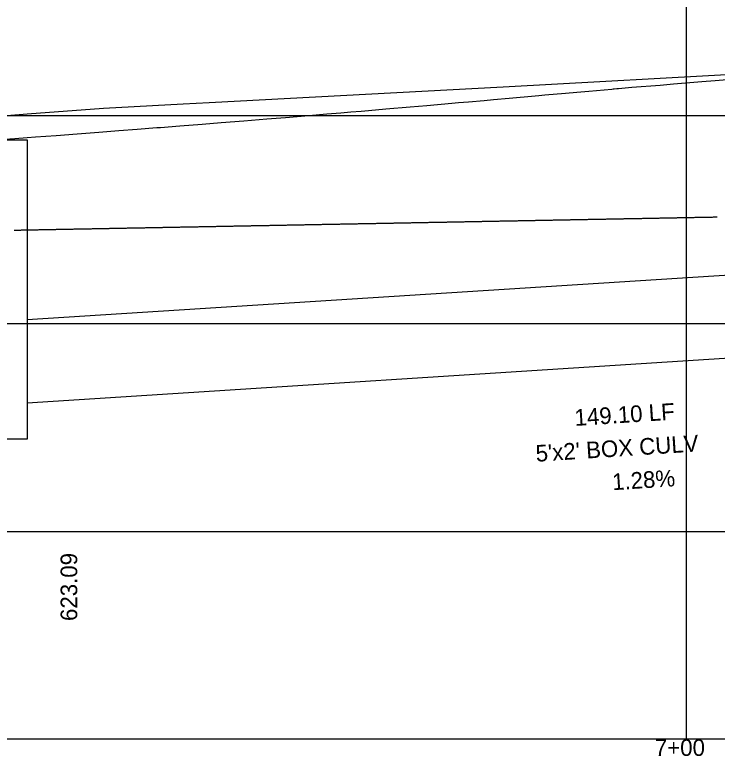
# Model space of a CAD drawing. Extents: x 2254979 to 2278074, y 13790855 to 13792793.
# Drawn here: x 2260580 to 2260664.4, y 13792139.4 to 13792228.5 of the extents above; entities that cross this region are included whole.
import ezdxf

# ---------------------------------------------------------------- set-up
doc = ezdxf.new("R2010")
doc.units = 0
for name, color, linetype in [('blank4', 7, 'Continuous'), ('D_DRN_PROF_HGL', 7, 'Continuous'), ('D_PROF_1', 7, 'Continuous'), ('D_PROF_NOTES_1', 7, 'Continuous'), ('Default', 7, 'Continuous'), ('Drain_PipeInside', 7, 'Continuous'), ('E_Terrain', 7, 'Continuous'), ('Inlet', 7, 'Continuous'), ('z - Construction', 7, 'Continuous')]:
    doc.layers.add(name, color=color, linetype=linetype)

msp = doc.modelspace()

# ---------------------------------------------------------------- linework, layer by layer
at = {"layer": 'blank4'}
msp.add_lwpolyline([(2259960.685, 13792141.443), (2259960.685, 13792316.443), (2261351.477, 13792316.443), (2261351.477, 13792141.443)], close=True, dxfattribs=at)
at = {"layer": 'D_DRN_PROF_HGL'}
msp.add_lwpolyline([(2260579.903, 13792202.657), (2260580.014, 13792202.66), (2260580.124, 13792202.662), (2260580.235, 13792202.664), (2260580.345, 13792202.666), (2260580.456, 13792202.668), (2260580.567, 13792202.67), (2260580.677, 13792202.672), (2260580.788, 13792202.674), (2260580.898, 13792202.676), (2260581.009, 13792202.678), (2260581.119, 13792202.68), (2260581.23, 13792202.682), (2260581.341, 13792202.684), (2260581.451, 13792202.687), (2260581.562, 13792202.689), (2260581.672, 13792202.691), (2260581.783, 13792202.693), (2260581.893, 13792202.695), (2260582.004, 13792202.697), (2260582.115, 13792202.699), (2260582.225, 13792202.701), (2260582.336, 13792202.703), (2260582.446, 13792202.705), (2260582.557, 13792202.707), (2260582.667, 13792202.709), (2260582.778, 13792202.712), (2260582.889, 13792202.714), (2260582.999, 13792202.716), (2260583.11, 13792202.718), (2260583.22, 13792202.72), (2260583.331, 13792202.722), (2260583.441, 13792202.724), (2260583.552, 13792202.726), (2260583.663, 13792202.728), (2260583.773, 13792202.73), (2260583.884, 13792202.732), (2260583.994, 13792202.734), (2260584.105, 13792202.736), (2260584.215, 13792202.739), (2260584.326, 13792202.741), (2260584.437, 13792202.743), (2260584.547, 13792202.745), (2260584.658, 13792202.747), (2260584.768, 13792202.749), (2260584.879, 13792202.751), (2260584.99, 13792202.753), (2260585.1, 13792202.755), (2260585.211, 13792202.757), (2260585.321, 13792202.759), (2260585.432, 13792202.761), (2260585.542, 13792202.763), (2260585.653, 13792202.766), (2260585.764, 13792202.768), (2260585.874, 13792202.77), (2260585.985, 13792202.772), (2260586.095, 13792202.774), (2260586.206, 13792202.776), (2260586.316, 13792202.778), (2260586.427, 13792202.78), (2260586.538, 13792202.782), (2260586.648, 13792202.784), (2260586.759, 13792202.786), (2260586.869, 13792202.788), (2260586.98, 13792202.791), (2260587.09, 13792202.793), (2260587.201, 13792202.795), (2260587.312, 13792202.797), (2260587.422, 13792202.799), (2260587.533, 13792202.801), (2260587.643, 13792202.803), (2260587.754, 13792202.805), (2260587.864, 13792202.807), (2260587.975, 13792202.809), (2260588.086, 13792202.811), (2260588.196, 13792202.813), (2260588.307, 13792202.815), (2260588.417, 13792202.818), (2260588.528, 13792202.82), (2260588.638, 13792202.822), (2260588.749, 13792202.824), (2260588.86, 13792202.826), (2260588.97, 13792202.828), (2260589.081, 13792202.83), (2260589.191, 13792202.832), (2260589.302, 13792202.834), (2260589.412, 13792202.836), (2260589.523, 13792202.838), (2260589.634, 13792202.84), (2260589.744, 13792202.842), (2260589.855, 13792202.845), (2260589.965, 13792202.847), (2260590.076, 13792202.849), (2260590.187, 13792202.851), (2260590.297, 13792202.853), (2260590.408, 13792202.855), (2260590.518, 13792202.857), (2260590.629, 13792202.859), (2260590.739, 13792202.861), (2260590.85, 13792202.863), (2260590.961, 13792202.865), (2260591.071, 13792202.867), (2260591.182, 13792202.869), (2260591.292, 13792202.872), (2260591.403, 13792202.874), (2260591.513, 13792202.876), (2260591.624, 13792202.878), (2260591.735, 13792202.88), (2260591.845, 13792202.882), (2260591.956, 13792202.884), (2260592.066, 13792202.886), (2260592.177, 13792202.888), (2260592.287, 13792202.89), (2260592.398, 13792202.892), (2260592.509, 13792202.894), (2260592.619, 13792202.897), (2260592.73, 13792202.899), (2260592.84, 13792202.901), (2260592.951, 13792202.903), (2260593.061, 13792202.905), (2260593.172, 13792202.907), (2260593.283, 13792202.909), (2260593.393, 13792202.911), (2260593.504, 13792202.913), (2260593.614, 13792202.915), (2260593.725, 13792202.917), (2260593.835, 13792202.919), (2260593.946, 13792202.921), (2260594.057, 13792202.924), (2260594.167, 13792202.926), (2260594.278, 13792202.928), (2260594.388, 13792202.93), (2260594.499, 13792202.932), (2260594.609, 13792202.934), (2260594.72, 13792202.936), (2260594.831, 13792202.938), (2260594.941, 13792202.94), (2260595.052, 13792202.942), (2260595.162, 13792202.944), (2260595.273, 13792202.946), (2260595.384, 13792202.948), (2260595.494, 13792202.951), (2260595.605, 13792202.953), (2260595.715, 13792202.955), (2260595.826, 13792202.957), (2260595.936, 13792202.959), (2260596.047, 13792202.961), (2260596.158, 13792202.963), (2260596.268, 13792202.965), (2260596.379, 13792202.967), (2260596.489, 13792202.969), (2260596.6, 13792202.971), (2260596.71, 13792202.973), (2260596.821, 13792202.976), (2260596.932, 13792202.978), (2260597.042, 13792202.98), (2260597.153, 13792202.982), (2260597.263, 13792202.984), (2260597.374, 13792202.986), (2260597.484, 13792202.988), (2260597.595, 13792202.99), (2260597.706, 13792202.992), (2260597.816, 13792202.994), (2260597.927, 13792202.996), (2260598.037, 13792202.998), (2260598.148, 13792203), (2260598.258, 13792203.003), (2260598.369, 13792203.005), (2260598.48, 13792203.007), (2260598.59, 13792203.009), (2260598.701, 13792203.011), (2260598.811, 13792203.013), (2260598.922, 13792203.015), (2260599.032, 13792203.017), (2260599.143, 13792203.019), (2260599.254, 13792203.021), (2260599.364, 13792203.023), (2260599.475, 13792203.025), (2260599.585, 13792203.027), (2260599.696, 13792203.03), (2260599.806, 13792203.032), (2260599.917, 13792203.034), (2260600.028, 13792203.036), (2260600.138, 13792203.038), (2260600.249, 13792203.04), (2260600.359, 13792203.042), (2260600.47, 13792203.044), (2260600.581, 13792203.046), (2260600.691, 13792203.048), (2260600.802, 13792203.05), (2260600.912, 13792203.052), (2260601.023, 13792203.054), (2260601.133, 13792203.057), (2260601.244, 13792203.059), (2260601.355, 13792203.061), (2260601.465, 13792203.063), (2260601.576, 13792203.065), (2260601.686, 13792203.067), (2260601.797, 13792203.069), (2260601.907, 13792203.071), (2260602.018, 13792203.073), (2260602.129, 13792203.075), (2260602.239, 13792203.077), (2260602.35, 13792203.079), (2260602.46, 13792203.082), (2260602.571, 13792203.084), (2260602.681, 13792203.086), (2260602.792, 13792203.088), (2260602.903, 13792203.09), (2260603.013, 13792203.092), (2260603.124, 13792203.094), (2260603.234, 13792203.096), (2260603.345, 13792203.098), (2260603.455, 13792203.1), (2260603.566, 13792203.102), (2260603.677, 13792203.104), (2260603.787, 13792203.106), (2260603.898, 13792203.109), (2260604.008, 13792203.111), (2260604.119, 13792203.113), (2260604.229, 13792203.115), (2260604.34, 13792203.117), (2260604.451, 13792203.119), (2260604.561, 13792203.121), (2260604.672, 13792203.123), (2260604.782, 13792203.125), (2260604.893, 13792203.127), (2260605.003, 13792203.129), (2260605.114, 13792203.131), (2260605.225, 13792203.133), (2260605.335, 13792203.136), (2260605.446, 13792203.138), (2260605.556, 13792203.14), (2260605.667, 13792203.142), (2260605.778, 13792203.144), (2260605.888, 13792203.146), (2260605.999, 13792203.148), (2260606.109, 13792203.15), (2260606.22, 13792203.152), (2260606.33, 13792203.154), (2260606.441, 13792203.156), (2260606.552, 13792203.158), (2260606.662, 13792203.16), (2260606.773, 13792203.163), (2260606.883, 13792203.165), (2260606.994, 13792203.167), (2260607.104, 13792203.169), (2260607.215, 13792203.171), (2260607.326, 13792203.173), (2260607.436, 13792203.175), (2260607.547, 13792203.177), (2260607.657, 13792203.179), (2260607.768, 13792203.181), (2260607.878, 13792203.183), (2260607.989, 13792203.185), (2260608.1, 13792203.188), (2260608.21, 13792203.19), (2260608.321, 13792203.192), (2260608.431, 13792203.194), (2260608.542, 13792203.196), (2260608.652, 13792203.198), (2260608.763, 13792203.2), (2260608.874, 13792203.202), (2260608.984, 13792203.204), (2260609.095, 13792203.206), (2260609.205, 13792203.208), (2260609.316, 13792203.21), (2260609.426, 13792203.212), (2260609.537, 13792203.215), (2260609.648, 13792203.217), (2260609.758, 13792203.219), (2260609.869, 13792203.221), (2260609.979, 13792203.223), (2260610.09, 13792203.225), (2260610.2, 13792203.227), (2260610.311, 13792203.229), (2260610.422, 13792203.231), (2260610.532, 13792203.233), (2260610.643, 13792203.235), (2260610.753, 13792203.237), (2260610.864, 13792203.239), (2260610.975, 13792203.242), (2260611.085, 13792203.244), (2260611.196, 13792203.246), (2260611.306, 13792203.248), (2260611.417, 13792203.25), (2260611.527, 13792203.252), (2260611.638, 13792203.254), (2260611.749, 13792203.256), (2260611.859, 13792203.258), (2260611.97, 13792203.26), (2260612.08, 13792203.262), (2260612.191, 13792203.264), (2260612.301, 13792203.267), (2260612.412, 13792203.269), (2260612.523, 13792203.271), (2260612.633, 13792203.273), (2260612.744, 13792203.275), (2260612.854, 13792203.277), (2260612.965, 13792203.279), (2260613.075, 13792203.281), (2260613.186, 13792203.283), (2260613.297, 13792203.285), (2260613.407, 13792203.287), (2260613.518, 13792203.289), (2260613.628, 13792203.291), (2260613.739, 13792203.294), (2260613.849, 13792203.296), (2260613.96, 13792203.298), (2260614.071, 13792203.3), (2260614.181, 13792203.302), (2260614.292, 13792203.304), (2260614.402, 13792203.306), (2260614.513, 13792203.308), (2260614.623, 13792203.31), (2260614.734, 13792203.312), (2260614.845, 13792203.314), (2260614.955, 13792203.316), (2260615.066, 13792203.318), (2260615.176, 13792203.321), (2260615.287, 13792203.323), (2260615.397, 13792203.325), (2260615.508, 13792203.327), (2260615.619, 13792203.329), (2260615.729, 13792203.331), (2260615.84, 13792203.333), (2260615.95, 13792203.335), (2260616.061, 13792203.337), (2260616.172, 13792203.339), (2260616.282, 13792203.341), (2260616.393, 13792203.343), (2260616.503, 13792203.345), (2260616.614, 13792203.348), (2260616.724, 13792203.35), (2260616.835, 13792203.352), (2260616.946, 13792203.354), (2260617.056, 13792203.356), (2260617.167, 13792203.358), (2260617.277, 13792203.36), (2260617.388, 13792203.362), (2260617.498, 13792203.364), (2260617.609, 13792203.366), (2260617.72, 13792203.368), (2260617.83, 13792203.37), (2260617.941, 13792203.373), (2260618.051, 13792203.375), (2260618.162, 13792203.377), (2260618.272, 13792203.379), (2260618.383, 13792203.381), (2260618.494, 13792203.383), (2260618.604, 13792203.385), (2260618.715, 13792203.387), (2260618.825, 13792203.389), (2260618.936, 13792203.391), (2260619.046, 13792203.393), (2260619.157, 13792203.395), (2260619.268, 13792203.397), (2260619.378, 13792203.4), (2260619.489, 13792203.402), (2260619.599, 13792203.404), (2260619.71, 13792203.406), (2260619.82, 13792203.408), (2260619.931, 13792203.41), (2260620.042, 13792203.412), (2260620.152, 13792203.414), (2260620.263, 13792203.416), (2260620.373, 13792203.418), (2260620.484, 13792203.42), (2260620.594, 13792203.422), (2260620.705, 13792203.424), (2260620.816, 13792203.427), (2260620.926, 13792203.429), (2260621.037, 13792203.431), (2260621.147, 13792203.433), (2260621.258, 13792203.435), (2260621.368, 13792203.437), (2260621.479, 13792203.439), (2260621.59, 13792203.441), (2260621.7, 13792203.443), (2260621.811, 13792203.445), (2260621.921, 13792203.447), (2260622.032, 13792203.449), (2260622.143, 13792203.452), (2260622.253, 13792203.454), (2260622.364, 13792203.456), (2260622.474, 13792203.458), (2260622.585, 13792203.46), (2260622.695, 13792203.462), (2260622.806, 13792203.464), (2260622.917, 13792203.466), (2260623.027, 13792203.468), (2260623.138, 13792203.47), (2260623.248, 13792203.472), (2260623.359, 13792203.474), (2260623.469, 13792203.476), (2260623.58, 13792203.479), (2260623.691, 13792203.481), (2260623.801, 13792203.483), (2260623.912, 13792203.485), (2260624.022, 13792203.487), (2260624.133, 13792203.489), (2260624.243, 13792203.491), (2260624.354, 13792203.493), (2260624.465, 13792203.495), (2260624.575, 13792203.497), (2260624.686, 13792203.499), (2260624.796, 13792203.501), (2260624.907, 13792203.503), (2260625.017, 13792203.506), (2260625.128, 13792203.508), (2260625.239, 13792203.51), (2260625.349, 13792203.512), (2260625.46, 13792203.514), (2260625.57, 13792203.516), (2260625.681, 13792203.518), (2260625.791, 13792203.52), (2260625.902, 13792203.522), (2260626.013, 13792203.524), (2260626.123, 13792203.526), (2260626.234, 13792203.528), (2260626.344, 13792203.53), (2260626.455, 13792203.533), (2260626.565, 13792203.535), (2260626.676, 13792203.537), (2260626.787, 13792203.539), (2260626.897, 13792203.541), (2260627.008, 13792203.543), (2260627.118, 13792203.545), (2260627.229, 13792203.547), (2260627.34, 13792203.549), (2260627.45, 13792203.551), (2260627.561, 13792203.553), (2260627.671, 13792203.555), (2260627.782, 13792203.558), (2260627.892, 13792203.56), (2260628.003, 13792203.562), (2260628.114, 13792203.564), (2260628.224, 13792203.566), (2260628.335, 13792203.568), (2260628.445, 13792203.57), (2260628.556, 13792203.572), (2260628.666, 13792203.574), (2260628.777, 13792203.576), (2260628.888, 13792203.578), (2260628.998, 13792203.58), (2260629.109, 13792203.582), (2260629.219, 13792203.585), (2260629.33, 13792203.587), (2260629.44, 13792203.589), (2260629.551, 13792203.591), (2260629.662, 13792203.593), (2260629.772, 13792203.595), (2260629.883, 13792203.597), (2260629.993, 13792203.599), (2260630.104, 13792203.601), (2260630.214, 13792203.603), (2260630.325, 13792203.605), (2260630.436, 13792203.607), (2260630.546, 13792203.609), (2260630.657, 13792203.612), (2260630.767, 13792203.614), (2260630.878, 13792203.616), (2260630.988, 13792203.618), (2260631.099, 13792203.62), (2260631.21, 13792203.622), (2260631.32, 13792203.624), (2260631.431, 13792203.626), (2260631.541, 13792203.628), (2260631.652, 13792203.63), (2260631.762, 13792203.632), (2260631.873, 13792203.634), (2260631.984, 13792203.637), (2260632.094, 13792203.639), (2260632.205, 13792203.641), (2260632.315, 13792203.643), (2260632.426, 13792203.645), (2260632.537, 13792203.647), (2260632.647, 13792203.649), (2260632.758, 13792203.651), (2260632.868, 13792203.653), (2260632.979, 13792203.655), (2260633.089, 13792203.657), (2260633.2, 13792203.659), (2260633.311, 13792203.661), (2260633.421, 13792203.664), (2260633.532, 13792203.666), (2260633.642, 13792203.668), (2260633.753, 13792203.67), (2260633.863, 13792203.672), (2260633.974, 13792203.674), (2260634.085, 13792203.676), (2260634.195, 13792203.678), (2260634.306, 13792203.68), (2260634.416, 13792203.682), (2260634.527, 13792203.684), (2260634.637, 13792203.686), (2260634.748, 13792203.688), (2260634.859, 13792203.691), (2260634.969, 13792203.693), (2260635.08, 13792203.695), (2260635.19, 13792203.697), (2260635.301, 13792203.699), (2260635.411, 13792203.701), (2260635.522, 13792203.703), (2260635.633, 13792203.705), (2260635.743, 13792203.707), (2260635.854, 13792203.709), (2260635.964, 13792203.711), (2260636.075, 13792203.713), (2260636.185, 13792203.715), (2260636.296, 13792203.718), (2260636.407, 13792203.72), (2260636.517, 13792203.722), (2260636.628, 13792203.724), (2260636.738, 13792203.726), (2260636.849, 13792203.728), (2260636.959, 13792203.73), (2260637.07, 13792203.732), (2260637.181, 13792203.734), (2260637.291, 13792203.736), (2260637.402, 13792203.738), (2260637.512, 13792203.74), (2260637.623, 13792203.743), (2260637.734, 13792203.745), (2260637.844, 13792203.747), (2260637.955, 13792203.749), (2260638.065, 13792203.751), (2260638.176, 13792203.753), (2260638.286, 13792203.755), (2260638.397, 13792203.757), (2260638.508, 13792203.759), (2260638.618, 13792203.761), (2260638.729, 13792203.763), (2260638.839, 13792203.765), (2260638.95, 13792203.767), (2260639.06, 13792203.77), (2260639.171, 13792203.772), (2260639.282, 13792203.774), (2260639.392, 13792203.776), (2260639.503, 13792203.778), (2260639.613, 13792203.78), (2260639.724, 13792203.782), (2260639.834, 13792203.784), (2260639.945, 13792203.786), (2260640.056, 13792203.788), (2260640.166, 13792203.79), (2260640.277, 13792203.792), (2260640.387, 13792203.794), (2260640.498, 13792203.797), (2260640.608, 13792203.799), (2260640.719, 13792203.801), (2260640.83, 13792203.803), (2260640.94, 13792203.805), (2260641.051, 13792203.807), (2260641.161, 13792203.809), (2260641.272, 13792203.811), (2260641.382, 13792203.813), (2260641.493, 13792203.815), (2260641.604, 13792203.817), (2260641.714, 13792203.819), (2260641.825, 13792203.821), (2260641.935, 13792203.824), (2260642.046, 13792203.826), (2260642.156, 13792203.828), (2260642.267, 13792203.83), (2260642.378, 13792203.832), (2260642.488, 13792203.834), (2260642.599, 13792203.836), (2260642.709, 13792203.838), (2260642.82, 13792203.84), (2260642.931, 13792203.842), (2260643.041, 13792203.844), (2260643.152, 13792203.846), (2260643.262, 13792203.849), (2260643.373, 13792203.851), (2260643.483, 13792203.853), (2260643.594, 13792203.855), (2260643.705, 13792203.857), (2260643.815, 13792203.859), (2260643.926, 13792203.861), (2260644.036, 13792203.863), (2260644.147, 13792203.865), (2260644.257, 13792203.867), (2260644.368, 13792203.869), (2260644.479, 13792203.871), (2260644.589, 13792203.873), (2260644.7, 13792203.876), (2260644.81, 13792203.878), (2260644.921, 13792203.88), (2260645.031, 13792203.882), (2260645.142, 13792203.884), (2260645.253, 13792203.886), (2260645.363, 13792203.888), (2260645.474, 13792203.89), (2260645.584, 13792203.892), (2260645.695, 13792203.894), (2260645.805, 13792203.896), (2260645.916, 13792203.898), (2260646.027, 13792203.9), (2260646.137, 13792203.903), (2260646.248, 13792203.905), (2260646.358, 13792203.907), (2260646.469, 13792203.909), (2260646.579, 13792203.911), (2260646.69, 13792203.913), (2260646.801, 13792203.915), (2260646.911, 13792203.917), (2260647.022, 13792203.919), (2260647.132, 13792203.921), (2260647.243, 13792203.923), (2260647.353, 13792203.925), (2260647.464, 13792203.928), (2260647.575, 13792203.93), (2260647.685, 13792203.932), (2260647.796, 13792203.934), (2260647.906, 13792203.936), (2260648.017, 13792203.938), (2260648.128, 13792203.94), (2260648.238, 13792203.942), (2260648.349, 13792203.944), (2260648.459, 13792203.946), (2260648.57, 13792203.948), (2260648.68, 13792203.95), (2260648.791, 13792203.952), (2260648.902, 13792203.955), (2260649.012, 13792203.957), (2260649.123, 13792203.959), (2260649.233, 13792203.961), (2260649.344, 13792203.963), (2260649.454, 13792203.965), (2260649.565, 13792203.967), (2260649.676, 13792203.969), (2260649.786, 13792203.971), (2260649.897, 13792203.973), (2260650.007, 13792203.975), (2260650.118, 13792203.977), (2260650.228, 13792203.979), (2260650.339, 13792203.982), (2260650.45, 13792203.984), (2260650.56, 13792203.986), (2260650.671, 13792203.988), (2260650.781, 13792203.99), (2260650.892, 13792203.992), (2260651.002, 13792203.994), (2260651.113, 13792203.996), (2260651.224, 13792203.998), (2260651.334, 13792204), (2260651.445, 13792204.002), (2260651.555, 13792204.004), (2260651.666, 13792204.006), (2260651.776, 13792204.009), (2260651.887, 13792204.011), (2260651.998, 13792204.013), (2260652.108, 13792204.015), (2260652.219, 13792204.017), (2260652.329, 13792204.019), (2260652.44, 13792204.021), (2260652.55, 13792204.023), (2260652.661, 13792204.025), (2260652.772, 13792204.027), (2260652.882, 13792204.029), (2260652.993, 13792204.031), (2260653.103, 13792204.034), (2260653.214, 13792204.036), (2260653.325, 13792204.038), (2260653.435, 13792204.04), (2260653.546, 13792204.042), (2260653.656, 13792204.044), (2260653.767, 13792204.046), (2260653.877, 13792204.048), (2260653.988, 13792204.05), (2260654.099, 13792204.052), (2260654.209, 13792204.054), (2260654.32, 13792204.056), (2260654.43, 13792204.058), (2260654.541, 13792204.061), (2260654.651, 13792204.063), (2260654.762, 13792204.065), (2260654.873, 13792204.067), (2260654.983, 13792204.069), (2260655.094, 13792204.071), (2260655.204, 13792204.073), (2260655.315, 13792204.075), (2260655.425, 13792204.077), (2260655.536, 13792204.079), (2260655.647, 13792204.081), (2260655.757, 13792204.083), (2260655.868, 13792204.085), (2260655.978, 13792204.088), (2260656.089, 13792204.09), (2260656.199, 13792204.092), (2260656.31, 13792204.094), (2260656.421, 13792204.096), (2260656.531, 13792204.098), (2260656.642, 13792204.1), (2260656.752, 13792204.102), (2260656.863, 13792204.104), (2260656.973, 13792204.106), (2260657.084, 13792204.108), (2260657.195, 13792204.11), (2260657.305, 13792204.113), (2260657.416, 13792204.115), (2260657.526, 13792204.117), (2260657.637, 13792204.119), (2260657.747, 13792204.121), (2260657.858, 13792204.123), (2260657.969, 13792204.125), (2260658.079, 13792204.127), (2260658.19, 13792204.129), (2260658.3, 13792204.131), (2260658.411, 13792204.133), (2260658.522, 13792204.135), (2260658.632, 13792204.137), (2260658.743, 13792204.14), (2260658.853, 13792204.142), (2260658.964, 13792204.144), (2260659.074, 13792204.146), (2260659.185, 13792204.148), (2260659.296, 13792204.15), (2260659.406, 13792204.152), (2260659.517, 13792204.154), (2260659.627, 13792204.156), (2260659.738, 13792204.158), (2260659.848, 13792204.16), (2260659.959, 13792204.162), (2260660.07, 13792204.164), (2260660.18, 13792204.167), (2260660.291, 13792204.169), (2260660.401, 13792204.171), (2260660.512, 13792204.173), (2260660.622, 13792204.175), (2260660.733, 13792204.177), (2260660.844, 13792204.179), (2260660.954, 13792204.181), (2260661.065, 13792204.183), (2260661.175, 13792204.185), (2260661.286, 13792204.187), (2260661.396, 13792204.189), (2260661.507, 13792204.191), (2260661.618, 13792204.194), (2260661.728, 13792204.196), (2260661.839, 13792204.198), (2260661.949, 13792204.2), (2260662.06, 13792204.202), (2260662.17, 13792204.204), (2260662.281, 13792204.206), (2260662.392, 13792204.208), (2260662.502, 13792204.21), (2260662.613, 13792204.212), (2260662.723, 13792204.214), (2260662.834, 13792204.216), (2260662.944, 13792204.219), (2260663.055, 13792204.221), (2260663.166, 13792204.223), (2260663.276, 13792204.225), (2260663.387, 13792204.227), (2260663.497, 13792204.229), (2260663.608, 13792204.231), (2260663.719, 13792204.233), (2260663.829, 13792204.235), (2260663.94, 13792204.237), (2260664.05, 13792204.239), (2260664.161, 13792204.241), (2260664.271, 13792204.243), (2260664.382, 13792204.246)], dxfattribs=at)
at = {"layer": 'D_PROF_1'}
msp.add_lwpolyline([(2260577.47, 13792213.497), (2260579.97, 13792213.681), (2260581.47, 13792213.791), (2260581.47, 13792213.791), (2260582.471, 13792213.865), (2260584.941, 13792214.05), (2260587.472, 13792214.24), (2260590.048, 13792214.436), (2260592.473, 13792214.621), (2260594.657, 13792214.791), (2260597.053, 13792214.977), (2260597.252, 13792214.992), (2260597.474, 13792215.009), (2260599.807, 13792215.194), (2260602.476, 13792215.405), (2260604.762, 13792215.589), (2260607.479, 13792215.807), (2260610.251, 13792216.033), (2260612.482, 13792216.216), (2260615.31, 13792216.45), (2260617.485, 13792216.632), (2260619.135, 13792216.77), (2260620.359, 13792216.873), (2260621.594, 13792216.978), (2260622.489, 13792217.054), (2260624.554, 13792217.232), (2260627.493, 13792217.484), (2260629.496, 13792217.659), (2260632.498, 13792217.92), (2260633.279, 13792217.989), (2260634.5, 13792218.096), (2260636.357, 13792218.26), (2260637.503, 13792218.362), (2260639.37, 13792218.527), (2260642.509, 13792218.804), (2260642.932, 13792218.842), (2260643.676, 13792218.908), (2260646.156, 13792219.127), (2260647.513, 13792219.247), (2260648.965, 13792219.375), (2260651.717, 13792219.619), (2260651.889, 13792219.634), (2260651.977, 13792219.642), (2260652.336, 13792219.673), (2260652.517, 13792219.689), (2260654.138, 13792219.825), (2260657.52, 13792220.102), (2260659.128, 13792220.237), (2260662.524, 13792220.515), (2260664.12, 13792220.649), (2260667.527, 13792220.928)], dxfattribs=at)
at = {"layer": 'Default'}
msp.add_line((2260660.685, 13792141.443), (2260660.685, 13792316.443), dxfattribs=at)
at = {"layer": 'Drain_PipeInside'}
for p, q in [((2260581.47, 13792191.898), (2260730.572, 13792201.443)), ((2260581.47, 13792181.898), (2260730.572, 13792191.443))]:
    msp.add_line(p, q, dxfattribs=at)
at = {"layer": 'E_Terrain'}
msp.add_lwpolyline([(2260577.47, 13792216.305), (2260581.47, 13792216.628), (2260581.47, 13792216.628), (2260590.632, 13792217.322), (2260600.206, 13792217.86), (2260603.32, 13792218.014), (2260638.64, 13792219.874), (2260669.149, 13792221.582), (2260700.382, 13792223.474), (2260700.415, 13792223.257), (2260730.572, 13792225.385), (2260730.572, 13792225.385), (2260734.572, 13792225.81), (2260734.572, 13792225.81), (2260738.572, 13792226.234)], dxfattribs=at)
at = {"layer": 'Inlet'}
msp.add_lwpolyline([(2260573.47, 13792213.497), (2260581.47, 13792213.497), (2260581.47, 13792177.539), (2260573.47, 13792177.539)], close=True, dxfattribs=at)
at = {"layer": 'z - Construction'}
for p, q in [((2259960.685, 13792216.443), (2261351.477, 13792216.443)), ((2259960.685, 13792191.443), (2261351.477, 13792191.443)), ((2259960.685, 13792166.443), (2261351.477, 13792166.443))]:
    msp.add_line(p, q, dxfattribs=at)

# ---------------------------------------------------------------- texts
at = {"layer": 'D_PROF_NOTES_1'}
for s, rotation, p in [('149.10 LF', 3.66289, (2260647.3, 13792179.114)), ("5'x2' BOX CULV", 3.66289, (2260642.624, 13792174.807)), ('1.28%', 3.66289, (2260651.809, 13792171.387)), ('623.09', 90, (2260587.47, 13792155.665))]:
    msp.add_text(s, height=2, rotation=rotation, dxfattribs=at).set_placement(p)
at = {"layer": 'Default'}
msp.add_text('7+00', height=2, dxfattribs=at).set_placement((2260656.883, 13792139.443))

doc.saveas('drawing.dxf')
